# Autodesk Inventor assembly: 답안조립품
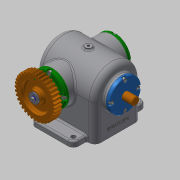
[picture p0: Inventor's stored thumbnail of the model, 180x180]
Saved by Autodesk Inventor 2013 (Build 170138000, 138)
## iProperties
Created: 2019-05
Part Number: 답안조립품
Document SubType Name: Assembly
Designer: Administrator
Author: Administrator
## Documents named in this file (16)
- C:\Users\Administrator\Desktop\390504V1046\답안조립품.iam
- C:\Users\Administrator\Desktop\390504V1046\본체.ipt
- C:\Users\Administrator\Desktop\390504V1046\가변스프링.ipt
- C:\Users\Administrator\Desktop\390504V1046\가이드부시.ipt
- C:\Users\Administrator\Desktop\390504V1046\베어링 6203.ipt
- C:\Users\Administrator\Desktop\390504V1046\볼트 M4x8.ipt
- C:\Users\Administrator\Desktop\390504V1046\볼트 M4x10.ipt
- C:\Users\Administrator\Desktop\390504V1046\스퍼기어.ipt
- C:\Users\Administrator\Desktop\390504V1046\스프링와셔.ipt
- C:\Users\Administrator\Desktop\390504V1046\슬라이더.ipt
- C:\Users\Administrator\Desktop\390504V1046\오일 실 17 32 8.ipt
- C:\Users\Administrator\Desktop\390504V1046\커버 A.ipt
- C:\Users\Administrator\Desktop\390504V1046\커버 B.ipt
- C:\Users\Administrator\Desktop\390504V1046\키 4x4x14.ipt
- C:\Users\Administrator\Desktop\390504V1046\편심축.ipt
- C:\Users\Administrator\Desktop\390504V1046\평와셔.ipt
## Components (2 placed, 2 different names)
1. 가변스프링:1
2. 가이드부시:1
